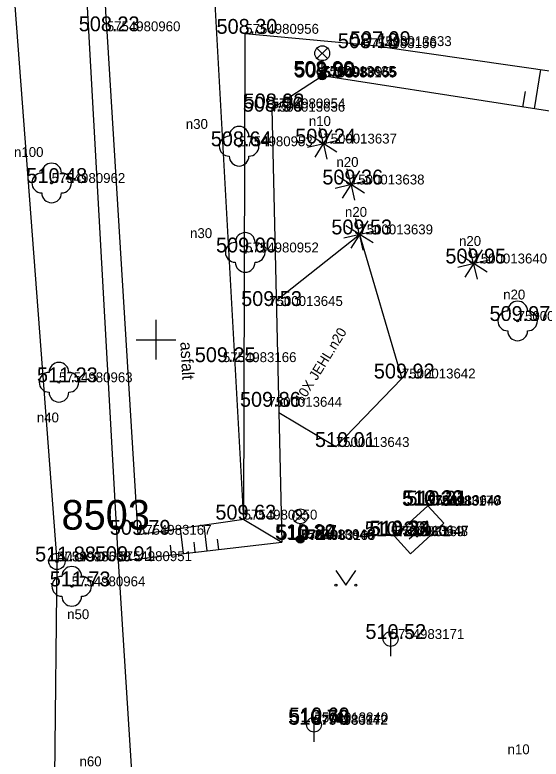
# Model space of a CAD drawing. Extents: x -669251 to -668549, y -1128351 to -1127698.
# Drawn here: x -669007.13 to -668980.55, y -1127821.19 to -1127783.58 of the extents above; entities that cross this region are included whole.
import ezdxf

# ---------------------------------------------------------------- set-up
doc = ezdxf.new("R2010")
doc.units = 0
for name, color, linetype in [('Vrstva 1', 7, 'Continuous'), ('Vrstva 10', 7, 'Continuous'), ('Vrstva 14', 7, 'Continuous'), ('Vrstva 15', 7, 'Continuous'), ('Vrstva 2', 7, 'Continuous'), ('Vrstva 21', 7, 'Continuous'), ('Vrstva 22', 7, 'Continuous'), ('Vrstva 24', 7, 'Continuous'), ('Vrstva 27', 7, 'Continuous'), ('Vrstva 3', 7, 'Continuous'), ('Vrstva 33', 7, 'Continuous'), ('Vrstva 36', 7, 'Continuous'), ('Vrstva 40', 7, 'Continuous'), ('Vrstva 47', 7, 'Continuous'), ('Vrstva 61', 7, 'Continuous'), ('Vrstva 63', 7, 'Continuous')]:
    doc.layers.add(name, color=color, linetype=linetype)

msp = doc.modelspace()

# ---------------------------------------------------------------- linework, layer by layer
at = {"layer": 'Vrstva 1'}
for p, q in [((-669002.484, -1127784.411), (-669002.484, -1127784.411)), ((-668995.488, -1127784.538), (-668995.488, -1127784.538)), ((-668989.54, -1127785.262), (-668989.54, -1127785.262)), ((-668988.782, -1127785.159), (-668988.782, -1127785.159)), ((-668991.603, -1127786.671), (-668991.603, -1127786.671)), ((-668991.58, -1127786.744), (-668991.58, -1127786.744)), ((-668991.532, -1127786.713), (-668991.532, -1127786.713)), ((-668994.161, -1127788.474), (-668994.161, -1127788.474)), ((-668994.154, -1127788.306), (-668994.154, -1127788.306)), ((-668991.548, -1127790.084), (-668991.548, -1127790.084)), ((-668995.801, -1127790.22), (-668995.801, -1127790.22)), ((-669005.27, -1127792.078), (-669005.27, -1127792.078)), ((-668990.154, -1127792.153), (-668990.154, -1127792.153)), ((-668989.724, -1127794.675), (-668989.724, -1127794.675)), ((-668995.492, -1127795.587), (-668995.492, -1127795.587)), ((-668983.962, -1127796.144), (-668983.962, -1127796.144)), ((-668994.278, -1127798.295), (-668994.278, -1127798.295)), ((-668981.731, -1127799.051), (-668981.731, -1127799.051)), ((-668996.621, -1127801.131), (-668996.621, -1127801.131)), ((-669004.901, -1127802.148), (-669004.901, -1127802.148)), ((-668987.575, -1127801.957), (-668987.575, -1127801.957)), ((-668994.317, -1127803.388), (-668994.317, -1127803.388)), ((-668990.913, -1127805.42), (-668990.913, -1127805.42)), ((-668986.31, -1127808.38), (-668986.31, -1127808.38)), ((-668986.265, -1127808.389), (-668986.265, -1127808.389)), ((-668986.259, -1127808.354), (-668986.259, -1127808.354)), ((-668995.567, -1127809.09), (-668995.567, -1127809.09)), ((-669000.912, -1127809.856), (-669000.912, -1127809.856)), ((-668992.712, -1127810.077), (-668992.712, -1127810.077)), ((-668992.684, -1127810.095), (-668992.684, -1127810.095)), ((-668988.146, -1127809.929), (-668988.146, -1127809.929)), ((-668987.957, -1127809.923), (-668987.957, -1127809.923)), ((-668987.923, -1127809.89), (-668987.923, -1127809.89)), ((-668992.644, -1127810.12), (-668992.644, -1127810.12)), ((-669004.995, -1127811.202), (-669004.995, -1127811.202)), ((-669004.98, -1127811.2), (-669004.98, -1127811.2)), ((-669001.902, -1127811.188), (-669001.902, -1127811.188)), ((-669004.255, -1127812.462), (-669004.255, -1127812.462)), ((-668988.148, -1127815.123), (-668988.148, -1127815.123)), ((-668992.021, -1127819.446), (-668992.021, -1127819.446)), ((-668992, -1127819.46), (-668992, -1127819.46)), ((-668991.991, -1127819.336), (-668991.991, -1127819.336))]:
    msp.add_line(p, q, dxfattribs=at)
at = {"layer": 'Vrstva 10'}
for p, q in [((-669002.484, -1127784.411), (-669003.824, -1127756.515)), ((-668995.567, -1127809.09), (-668997.053, -1127782.271)), ((-669002.484, -1127784.411), (-669000.912, -1127809.856)), ((-668995.567, -1127809.09), (-669000.912, -1127809.856))]:
    msp.add_line(p, q, dxfattribs=at)
at = {"layer": 'Vrstva 14'}
for p, q in [((-669004.995, -1127811.202), (-669007.118, -1127783.121)), ((-668995.567, -1127809.09), (-668995.488, -1127784.538)), ((-668988.782, -1127785.159), (-668995.488, -1127784.538)), ((-668988.782, -1127785.159), (-668976.618, -1127786.912)), ((-668994.154, -1127788.306), (-668991.603, -1127786.671)), ((-668994.154, -1127788.306), (-668993.636, -1127810.234)), ((-668995.567, -1127809.09), (-668993.636, -1127810.234)), ((-669001.902, -1127811.188), (-668993.636, -1127810.234)), ((-669005.286, -1127839.263), (-669004.995, -1127811.202)), ((-669001.902, -1127811.188), (-669000.855, -1127828.073))]:
    msp.add_line(p, q, dxfattribs=at)
for points in [[(-669004.988, -1127756.361), (-669003.445, -1127783.774), (-669001.902, -1127811.188)], [(-668967.135, -1127764.819), (-668967.2, -1127768.385), (-668967.265, -1127771.952), (-668967.365, -1127774.255), (-668967.507, -1127775.978), (-668967.806, -1127778.558), (-668968.178, -1127781.137), (-668968.317, -1127781.862), (-668968.675, -1127783.089), (-668969.029, -1127783.983), (-668969.674, -1127785.301), (-668970.432, -1127786.617), (-668971.022, -1127787.623), (-668971.509, -1127788.374), (-668971.912, -1127788.865), (-668972.239, -1127789.163), (-668972.501, -1127789.334), (-668972.924, -1127789.488), (-668973.15, -1127789.511), (-668973.386, -1127789.495), (-668982.495, -1127788.083), (-668991.603, -1127786.671)]]:
    msp.add_lwpolyline(points, dxfattribs=at)
at = {"layer": 'Vrstva 15'}
for p, q in [((-668980.871, -1127788.335), (-668980.562, -1127786.344)), ((-668981.463, -1127788.243), (-668981.34, -1127787.449)), ((-668998.613, -1127810.808), (-668998.758, -1127809.547)), ((-668997.421, -1127810.671), (-668997.57, -1127809.377)), ((-668996.825, -1127810.602), (-668996.885, -1127810.078)), ((-668999.208, -1127810.877), (-668999.266, -1127810.379)), ((-668998.016, -1127810.74), (-668998.075, -1127810.229))]:
    msp.add_line(p, q, dxfattribs=at)
at = {"layer": 'Vrstva 21'}
for p, q in [((-668993.925, -1127798.014), (-668989.724, -1127794.675)), ((-668989.724, -1127794.675), (-668987.575, -1127801.957)), ((-668987.575, -1127801.957), (-668990.913, -1127805.42)), ((-668990.913, -1127805.42), (-668993.79, -1127803.702))]:
    msp.add_line(p, q, dxfattribs=at)
at = {"layer": 'Vrstva 22'}
for p, q in [((-668991.556, -1127790.044), (-668991.728, -1127789.29)), ((-668991.114, -1127789.394), (-668991.528, -1127790.05)), ((-668991.582, -1127790.064), (-668992.238, -1127789.65)), ((-668992.342, -1127790.264), (-668991.588, -1127790.092)), ((-668991.568, -1127790.118), (-668991.982, -1127790.774)), ((-668991.54, -1127790.124), (-668991.368, -1127790.878)), ((-668990.858, -1127790.518), (-668991.514, -1127790.104)), ((-668991.508, -1127790.076), (-668990.754, -1127789.904)), ((-668990.162, -1127792.113), (-668990.334, -1127791.359)), ((-668989.72, -1127791.463), (-668990.134, -1127792.119)), ((-668990.188, -1127792.133), (-668990.844, -1127791.719)), ((-668990.114, -1127792.145), (-668989.36, -1127791.973)), ((-668990.948, -1127792.333), (-668990.194, -1127792.161)), ((-668990.174, -1127792.187), (-668990.588, -1127792.843)), ((-668990.146, -1127792.193), (-668989.974, -1127792.947)), ((-668989.464, -1127792.587), (-668990.12, -1127792.173)), ((-668989.732, -1127794.635), (-668989.904, -1127793.881)), ((-668989.758, -1127794.655), (-668990.414, -1127794.241)), ((-668989.29, -1127793.985), (-668989.704, -1127794.641)), ((-668990.518, -1127794.855), (-668989.764, -1127794.683)), ((-668989.684, -1127794.667), (-668988.93, -1127794.495)), ((-668989.744, -1127794.709), (-668990.158, -1127795.365)), ((-668989.716, -1127794.715), (-668989.544, -1127795.469)), ((-668989.034, -1127795.109), (-668989.69, -1127794.695)), ((-668983.97, -1127796.104), (-668984.142, -1127795.35)), ((-668983.996, -1127796.124), (-668984.652, -1127795.71)), ((-668983.528, -1127795.454), (-668983.942, -1127796.11)), ((-668984.756, -1127796.324), (-668984.002, -1127796.152)), ((-668983.982, -1127796.178), (-668984.396, -1127796.834)), ((-668983.954, -1127796.184), (-668983.782, -1127796.938)), ((-668983.272, -1127796.578), (-668983.928, -1127796.164)), ((-668983.922, -1127796.136), (-668983.168, -1127795.964))]:
    msp.add_line(p, q, dxfattribs=at)
for centre, radius in [((-668995.801, -1127790.22), 0.05), ((-668991.548, -1127790.084), 0.04), ((-669005.27, -1127792.078), 0.05), ((-668990.154, -1127792.153), 0.04), ((-668989.724, -1127794.675), 0.04), ((-668995.492, -1127795.587), 0.05), ((-668983.962, -1127796.144), 0.04), ((-668981.731, -1127799.051), 0.05), ((-669004.901, -1127802.148), 0.05), ((-669004.255, -1127812.462), 0.05)]:
    msp.add_circle(centre, radius, dxfattribs=at)
for centre, start, end in [((-668995.801, -1127789.72), 0, 180), ((-668996.301, -1127790.22), 90, 270), ((-668995.301, -1127790.22), 270, 90), ((-668995.801, -1127790.72), 180, 0), ((-669005.27, -1127791.578), 0, 180), ((-669005.77, -1127792.078), 90, 270), ((-669004.77, -1127792.078), 270, 90), ((-669005.27, -1127792.578), 180, 0), ((-668995.492, -1127795.087), 0, 180), ((-668995.992, -1127795.587), 90, 270), ((-668994.992, -1127795.587), 270, 90), ((-668995.492, -1127796.087), 180, 0), ((-668981.731, -1127798.551), 0, 180), ((-668982.231, -1127799.051), 90, 270), ((-668981.231, -1127799.051), 270, 90), ((-668981.731, -1127799.551), 180, 0), ((-669004.901, -1127801.648), 0, 180), ((-669005.401, -1127802.148), 90, 270), ((-669004.401, -1127802.148), 270, 90), ((-669004.901, -1127802.648), 180, 0), ((-669004.255, -1127811.962), 0, 180), ((-669004.755, -1127812.462), 90, 270), ((-669003.755, -1127812.462), 270, 90), ((-669004.255, -1127812.962), 180, 0)]:
    msp.add_arc(centre, 0.5, start, end, dxfattribs=at)
at = {"layer": 'Vrstva 24'}
for p, q in [((-668986.265, -1127808.389), (-668987.957, -1127809.923)), ((-668985.459, -1127809.278), (-668986.265, -1127808.389)), ((-668985.459, -1127809.278), (-668987.151, -1127810.812)), ((-668987.151, -1127810.812), (-668987.957, -1127809.923))]:
    msp.add_line(p, q, dxfattribs=at)
msp.add_lwpolyline([(-668987.213, -1127810.07), (-668986.94, -1127809.824), (-668986.817, -1127809.959), (-668986.408, -1127809.588), (-668986.53, -1127809.452), (-668986.258, -1127809.204)], dxfattribs=at)
at = {"layer": 'Vrstva 27'}
for p, q in [((-668988.148, -1127814.748), (-668988.148, -1127815.998)), ((-668992.02, -1127819.075), (-668992.02, -1127820.325))]:
    msp.add_line(p, q, dxfattribs=at)
for centre in [(-668988.148, -1127815.123), (-668992.02, -1127819.45)]:
    msp.add_circle(centre, 0.375, dxfattribs=at)
at = {"layer": 'Vrstva 33'}
for p, q in [((-668991.868, -1127785.256), (-668991.338, -1127785.786)), ((-668991.868, -1127785.786), (-668991.338, -1127785.256)), ((-668991.603, -1127786.671), (-668991.603, -1127785.896)), ((-668992.977, -1127808.662), (-668992.447, -1127809.192)), ((-668992.977, -1127809.192), (-668992.447, -1127808.662)), ((-668992.712, -1127810.077), (-668992.712, -1127809.302))]:
    msp.add_line(p, q, dxfattribs=at)
for centre, radius in [((-668991.603, -1127785.521), 0.375), ((-668991.603, -1127786.671), 0.2), ((-668991.603, -1127786.671), 0.18), ((-668991.603, -1127786.671), 0.16), ((-668991.603, -1127786.671), 0.14), ((-668991.603, -1127786.671), 0.12), ((-668991.603, -1127786.671), 0.1), ((-668991.603, -1127786.671), 0.08), ((-668991.603, -1127786.671), 0.06), ((-668991.603, -1127786.671), 0.04), ((-668991.603, -1127786.671), 0.02), ((-668992.712, -1127808.927), 0.375), ((-668992.712, -1127810.077), 0.2), ((-668992.712, -1127810.077), 0.18), ((-668992.712, -1127810.077), 0.16), ((-668992.712, -1127810.077), 0.14), ((-668992.712, -1127810.077), 0.12), ((-668992.712, -1127810.077), 0.1), ((-668992.712, -1127810.077), 0.08), ((-668992.712, -1127810.077), 0.06), ((-668992.712, -1127810.077), 0.04), ((-668992.712, -1127810.077), 0.02)]:
    msp.add_circle(centre, radius, dxfattribs=at)
at = {"layer": 'Vrstva 36'}
for p, q in [((-668990.907, -1127811.659), (-668990.407, -1127812.409)), ((-668990.407, -1127812.409), (-668989.907, -1127811.659))]:
    msp.add_line(p, q, dxfattribs=at)
for centre in [(-668990.907, -1127812.409), (-668989.907, -1127812.409)]:
    msp.add_circle(centre, 0.05, dxfattribs=at)
at = {"layer": 'Vrstva 61'}
for p, q in [((-669000, -1127799), (-669000, -1127801)), ((-669001, -1127800), (-668999, -1127800))]:
    msp.add_line(p, q, dxfattribs=at)
at = {"layer": 'Vrstva 63'}
for radius in [0.412, 0.412, 0.05, 0.05]:
    msp.add_circle((-669005, -1127811.2), radius, dxfattribs=at)

# ---------------------------------------------------------------- texts
at = {"layer": 'Vrstva 2'}
for s, p in [('5754980960', (-669002.484, -1127784.411)), ('5754980956', (-668995.488, -1127784.538)), ('5754983156', (-668989.54, -1127785.262)), ('7500013633', (-668988.782, -1127785.159)), ('7500013635', (-668991.603, -1127786.671)), ('5754983165', (-668991.58, -1127786.744)), ('5754980955', (-668991.532, -1127786.713)), ('5754980954', (-668994.154, -1127788.306)), ('7500013636', (-668994.161, -1127788.474)), ('5754980953', (-668995.801, -1127790.22)), ('7500013637', (-668991.548, -1127790.084)), ('5754980962', (-669005.27, -1127792.078)), ('7500013638', (-668990.154, -1127792.153)), ('7500013639', (-668989.724, -1127794.675)), ('5754980952', (-668995.492, -1127795.587)), ('7500013640', (-668983.962, -1127796.144)), ('7500013645', (-668994.278, -1127798.295)), ('7500013641', (-668981.731, -1127799.051)), ('5754983166', (-668996.621, -1127801.131)), ('7500013642', (-668987.575, -1127801.957)), ('5754980963', (-669004.901, -1127802.148)), ('7500013644', (-668994.317, -1127803.388)), ('7500013643', (-668990.913, -1127805.42)), ('7500013648', (-668986.259, -1127808.354)), ('5754983170', (-668986.31, -1127808.38)), ('5754980947', (-668986.265, -1127808.389)), ('5754980950', (-668995.567, -1127809.09)), ('5754983167', (-669000.912, -1127809.856)), ('7500013646', (-668992.712, -1127810.077)), ('5754980949', (-668992.684, -1127810.095)), ('5754983168', (-668992.644, -1127810.12)), ('5754983169', (-668988.146, -1127809.929)), ('5754980948', (-668987.957, -1127809.923)), ('7500013647', (-668987.923, -1127809.89)), ('5754998503', (-669004.995, -1127811.202)), ('4039915030', (-669004.98, -1127811.2)), ('5754980951', (-669001.902, -1127811.188)), ('5754980964', (-669004.255, -1127812.462)), ('5754983171', (-668988.148, -1127815.123)), ('5754980942', (-668992.021, -1127819.446)), ('5754983172', (-668992, -1127819.46)), ('7500013240', (-668991.991, -1127819.336))]:
    msp.add_text(s, height=0.5, dxfattribs=at).set_placement(p)
at = {"layer": 'Vrstva 3'}
for s, p in [('508.23 ', (-669003.899, -1127784.411)), ('508.30 ', (-668996.939, -1127784.538)), ('508.18 ', (-668990.814, -1127785.262)), ('507.99 ', (-668990.202, -1127785.159)), ('508.90 ', (-668993.056, -1127786.671)), ('509.05 ', (-668993.018, -1127786.744)), ('509.00 ', (-668993.006, -1127786.713)), ('508.90 ', (-668995.614, -1127788.474)), ('508.92 ', (-668995.571, -1127788.306)), ('509.24 ', (-668992.965, -1127790.084)), ('508.64 ', (-668997.23, -1127790.22)), ('510.48 ', (-669006.544, -1127792.078)), ('509.36 ', (-668991.594, -1127792.153)), ('509.53 ', (-668991.141, -1127794.675)), ('509.00 ', (-668996.966, -1127795.587)), ('509.95 ', (-668985.381, -1127796.144)), ('509.53 ', (-668995.695, -1127798.295)), ('509.97 ', (-668983.15, -1127799.051)), ('509.25 ', (-668998.038, -1127801.131)), ('511.23 ', (-669006.011, -1127802.148)), ('509.92 ', (-668988.994, -1127801.957)), ('509.86 ', (-668995.757, -1127803.388)), ('510.01 ', (-668991.971, -1127805.42)), ('510.30 ', (-668987.574, -1127808.389)), ('510.22 ', (-668987.533, -1127808.354)), ('510.21 ', (-668987.347, -1127808.38)), ('509.63 ', (-668996.998, -1127809.09)), ('509.79 ', (-669002.332, -1127809.856)), ('510.29 ', (-668993.988, -1127810.077)), ('510.34 ', (-668993.958, -1127810.095)), ('510.20 ', (-668989.455, -1127809.929)), ('510.33 ', (-668989.231, -1127809.923)), ('510.24 ', (-668989.197, -1127809.89)), ('510.27 ', (-668993.918, -1127810.12)), ('511.88 ', (-669006.105, -1127811.202)), ('509.91 ', (-669003.084, -1127811.188)), ('511.73 ', (-669005.365, -1127812.462)), ('510.52 ', (-668989.422, -1127815.123)), ('510.70 ', (-668993.33, -1127819.446)), ('510.76 ', (-668993.296, -1127819.46)), ('510.69 ', (-668993.281, -1127819.336))]:
    msp.add_text(s, height=0.75, dxfattribs=at).set_placement(p)
at = {"layer": 'Vrstva 40'}
msp.add_text('asfalt', height=0.6, rotation=273.1714, dxfattribs=at).set_placement((-668998.773, -1127800.122))
at = {"layer": 'Vrstva 47'}
for s, height, p in [('n30', 0.5, (-668998.492, -1127789.344)), ('n10', 0.5, (-668992.278, -1127789.198)), ('n100', 0.5, (-669007.17, -1127790.763)), ('n20', 0.5, (-668990.884, -1127791.267)), ('n20', 0.5, (-668990.454, -1127793.789)), ('n30', 0.5, (-668998.278, -1127794.863)), ('n20', 0.5, (-668984.692, -1127795.258)), ('n20', 0.499, (-668982.46, -1127797.965)), ('n40', 0.5, (-669006.017, -1127804.178)), ('n50', 0.5, (-669004.486, -1127814.121)), ('n10', 0.5, (-668982.239, -1127820.949)), ('n60', 0.5, (-669003.86, -1127821.558))]:
    msp.add_text(s, height=height, dxfattribs=at).set_placement(p)
msp.add_text('10X JEHL.n20', height=0.5, rotation=58.266, dxfattribs=at).set_placement((-668992.608, -1127803.262))
at = {"layer": 'Vrstva 63'}
msp.add_text('8503', height=1.5, dxfattribs=at).set_placement((-669004.769, -1127809.6))

doc.saveas('drawing.dxf')
